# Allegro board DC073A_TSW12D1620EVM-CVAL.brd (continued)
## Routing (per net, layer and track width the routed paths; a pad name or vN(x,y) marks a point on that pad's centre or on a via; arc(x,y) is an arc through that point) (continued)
DQD5+: length 81.3
  L08_SIG2 w0.076: v1(131.44,94.72) 131.44,94.28 131.52,94.2 131.83,94.2 132.21,93.83 132.21,93.04 131.66,92.49 130.53,92.49 126.01,97.02 111.13,97.02 110.7,96.58 109.96,96.58 109.67,96.88 109.67,97.29 109.52,97.45 108.99,97.45 108.83,97.29 108.83,96.88 108.54,96.58 107.81,96.58 107.51,96.88 107.51,97.29 107.36,97.45 106.83,97.45 106.67,97.29 106.67,96.88 106.38,96.58 105.65,96.58 105.35,96.88 105.35,97.29 105.2,97.45 104.67,97.45 104.51,97.29 104.51,96.88 104.22,96.58 103.59,96.58 103.19,96.98 103.19,97.29 103.04,97.45 100.84,97.45 98.52,99.77 88.19,99.77 87.26,98.84 87.26,92.76 89.17,90.85 89.17,80.27 87.39,78.49 87.39,75.46 86.99,75.06 86.56,75.06 86.49,74.99 v1(86.49,74.55)
DQD5-: length 81.3
  L08_SIG2 w0.076: v1(131.44,93.45) 131.44,93.88 131.52,93.96 131.73,93.96 131.97,93.73 131.97,93.14 131.56,92.74 130.63,92.74 130.47,92.9 130.47,93.06 130.55,93.14 130.55,93.3 130.44,93.41 130.28,93.41 130.2,93.33 130.04,93.33 126.11,97.26 111.03,97.26 110.6,96.82 110.06,96.82 109.91,96.98 109.91,97.39 109.62,97.69 108.89,97.69 108.59,97.39 108.59,96.98 108.44,96.82 107.91,96.82 107.75,96.98 107.75,97.39 107.46,97.69 106.73,97.69 106.43,97.39 106.43,96.98 106.28,96.82 105.75,96.82 105.59,96.98 105.59,97.39 105.3,97.69 104.57,97.69 104.27,97.39 104.27,96.98 104.12,96.82 103.69,96.82 103.44,97.08 103.44,97.39 103.14,97.69 100.94,97.69 98.62,100.01 88.09,100.01 87.02,98.94 87.02,92.66 88.93,90.75 88.93,81.08 88.75,80.9 88.75,80.79 88.93,80.62 88.93,80.37 87.15,78.59 87.15,76.83 86.87,76.56 86.87,76.35 87.15,76.07 87.15,75.56 86.89,75.3 86.56,75.3 86.49,75.38 v1(86.49,75.82)
DQD6+: length 81.1
  L10_SIG3 w0.076: v1(87.76,73.28) 87.76,73.68 87.63,73.81 87.31,73.81 86.97,74.14 86.97,77.32 87.45,77.8 111.37,77.8 112.51,78.94 113.19,78.94 114.4,77.73 114.85,77.73 118.41,81.29 118.41,81.51 118.03,81.88 117.81,81.88 114.95,79.02 114.53,79.02 114.01,79.54 114.01,79.86 119.34,85.19 119.68,85.19 120.16,84.71 120.36,84.71 120.73,85.08 120.73,85.3 120.25,85.78 120.25,86.19 120.77,86.71 121.19,86.71 121.67,86.23 121.88,86.23 122.26,86.61 122.26,86.83 121.78,87.31 121.78,87.72 122.3,88.24 122.72,88.24 123.2,87.76 123.41,87.76 123.79,88.14 123.79,88.35 123.31,88.83 123.31,89.25 123.83,89.77 124.3,89.77 124.78,89.29 124.94,89.29 125.32,89.67 125.32,89.88 124.84,90.36 124.84,90.78 125.36,91.3 125.77,91.3 126.25,90.82 126.47,90.82 126.84,91.19 126.84,91.41 126.36,91.89 126.36,92.3 126.88,92.82 127.3,92.82 127.78,92.34 127.99,92.34 128.37,92.72 128.37,92.94 127.89,93.42 127.89,93.83 129.53,95.47 132.64,95.47 132.72,95.55 v1(132.72,95.99)
DQD6-: length 81.1
  L10_SIG3 w0.076: v1(87.76,74.55) 87.76,74.15 87.66,74.05 87.41,74.05 87.21,74.24 87.21,74.88 87.28,74.95 87.44,74.95 87.5,75.02 87.5,75.21 87.43,75.29 87.29,75.29 87.21,75.36 87.21,77.22 87.55,77.56 88.13,77.56 88.2,77.49 88.2,77.33 88.27,77.27 88.47,77.27 88.54,77.34 88.54,77.49 88.61,77.56 111.47,77.56 112.61,78.7 113.09,78.7 114.3,77.49 114.95,77.49 118.65,81.19 118.65,81.61 118.13,82.12 117.71,82.12 114.85,79.26 114.63,79.26 114.26,79.64 114.26,79.76 119.44,84.94 119.58,84.94 120.06,84.46 120.46,84.46 120.98,84.98 120.98,85.4 120.5,85.88 120.5,86.09 120.87,86.47 121.09,86.47 121.57,85.99 121.98,85.99 122.5,86.51 122.5,86.93 122.02,87.41 122.02,87.62 122.4,88 122.62,88 123.1,87.52 123.51,87.52 124.03,88.04 124.03,88.45 123.55,88.93 123.55,89.15 123.93,89.53 124.2,89.53 124.68,89.05 125.04,89.05 125.56,89.57 125.56,89.98 125.08,90.46 125.08,90.68 125.46,91.05 125.67,91.05 126.15,90.58 126.57,90.58 127.09,91.09 127.09,91.51 126.61,91.99 126.61,92.2 126.98,92.58 127.2,92.58 127.68,92.1 128.09,92.1 128.61,92.62 128.61,93.04 128.13,93.52 128.13,93.73 129.63,95.23 132.64,95.23 132.72,95.15 v1(132.72,94.72)
DQD7+: length 81.1
  L10_SIG3 w0.076: v1(136.53,94.72) 136.53,94.28 136.6,94.2 136.82,94.2 137.06,94.44 137.06,94.95 136.8,95.21 136.12,95.21 136.05,95.14 136.05,94.91 135.98,94.84 135.84,94.84 135.76,94.92 135.76,95.14 135.7,95.21 133.87,95.21 133.55,94.89 133.55,94.44 133.09,93.97 131.29,93.97 129.43,92.11 129.43,88.19 128.46,87.22 127.52,87.22 126.57,88.17 126.35,88.17 120.54,82.36 120.54,82.14 120.91,81.76 121.13,81.76 126.25,86.89 126.67,86.89 127.19,86.37 127.19,85.95 117.59,76.35 87.89,76.35 87.76,76.22 v1(87.76,75.82)
DQD7-: length 81.3
  L10_SIG3 w0.076: v1(87.76,77.09) 87.76,76.69 87.85,76.59 117.49,76.59 126.95,86.05 126.95,86.27 126.57,86.65 126.35,86.65 121.23,81.52 120.81,81.52 120.3,82.04 120.3,82.46 126.25,88.42 126.67,88.42 127.62,87.46 128.36,87.46 129.18,88.29 129.18,92.21 131.19,94.22 132.99,94.22 133.31,94.54 133.31,94.99 133.77,95.45 136.9,95.45 137.3,95.05 137.3,94.34 136.93,93.96 136.6,93.96 136.53,93.88 v1(136.53,93.45)
DQD8+: length 81.3
  L10_SIG3 w0.076: v1(89.03,74.55) 89.03,74.99 89.1,75.06 89.27,75.06 89.52,74.82 89.52,71.02 90.28,70.26 90.69,70.26 92.13,71.7 92.35,71.7 92.72,71.32 92.72,71.04 91.29,69.61 91.29,69.24 91.79,68.74 92.19,68.74 93.63,70.17 93.87,70.17 94.25,69.8 94.25,69.58 92.81,68.14 92.81,67.73 93.7,66.84 116.41,66.84 138.62,89.05 138.62,95.12 138.27,95.47 137.87,95.47 137.79,95.55 v1(137.79,95.99)
DQD8-: length 81.3
  L10_SIG3 w0.076: v1(89.03,75.82) 89.03,75.38 89.1,75.3 89.37,75.3 89.76,74.92 89.76,71.12 90.38,70.5 90.59,70.5 92.03,71.94 92.45,71.94 92.97,71.42 92.97,70.94 91.53,69.51 91.53,69.34 91.89,68.98 92.09,68.98 93.53,70.41 93.97,70.41 94.49,69.9 94.49,69.48 93.06,68.04 93.06,67.83 93.8,67.08 94.18,67.08 94.25,67.15 94.25,67.19 94.32,67.26 94.41,67.26 94.48,67.19 94.48,67.15 94.54,67.08 116.31,67.08 138.38,89.15 138.38,89.38 138.3,89.46 138.23,89.46 138.15,89.53 138.15,89.76 138.23,89.84 138.3,89.84 138.38,89.92 138.38,93.9 138.3,93.97 138.18,93.97 138.1,94.05 138.1,94.28 138.18,94.35 138.3,94.35 138.38,94.43 138.38,95.02 138.17,95.23 137.87,95.23 137.79,95.15 v1(137.79,94.72)
DQD9+: length 81.3
  L10_SIG3 w0.076: v1(90.3,73.28) 90.3,73.61 90.47,73.79 94.4,73.79 94.65,73.53 94.65,72.53 96.33,70.85 97.96,70.85 98.25,71.15 98.25,72.58 98.4,72.73 98.94,72.73 99.09,72.58 99.09,71.15 99.38,70.85 100.12,70.85 100.41,71.15 100.41,72.58 100.56,72.73 101.1,72.73 101.25,72.58 101.25,71.15 101.54,70.85 102.28,70.85 102.57,71.15 102.57,72.58 102.72,72.73 103.25,72.73 103.41,72.58 103.41,71.15 103.7,70.85 104.43,70.85 104.73,71.15 104.73,72.58 104.88,72.73 105.41,72.73 105.57,72.58 105.57,71.15 105.86,70.85 106.59,70.85 106.89,71.15 106.89,72.58 107.04,72.73 107.57,72.73 107.72,72.58 107.72,71.15 108.02,70.85 108.75,70.85 109.05,71.15 109.05,72.58 109.2,72.73 109.73,72.73 109.88,72.58 109.88,71.15 110.18,70.85 110.91,70.85 111.2,71.15 111.2,72.58 111.36,72.73 111.89,72.73 112.04,72.58 112.04,71.15 112.34,70.85 113.07,70.85 113.36,71.15 113.36,72.58 113.52,72.73 114.05,72.73 114.2,72.58 114.2,71.15 114.65,70.7 116.14,70.7 132.11,86.66 132.11,90.07 131.78,90.39 131.52,90.39 131.44,90.47 v1(131.44,90.91)
DQD9-: length 81.1
  L10_SIG3 w0.076: v1(131.44,89.64) 131.44,90.07 131.52,90.15 131.68,90.15 131.86,89.97 131.86,89.25 131.75,89.13 131.71,89.13 131.6,89.02 131.6,88.86 131.71,88.75 131.75,88.75 131.86,88.64 131.86,87.61 131.75,87.5 131.68,87.5 131.57,87.38 131.57,87.23 131.68,87.11 131.75,87.11 131.86,87 131.86,86.76 116.04,70.94 114.75,70.94 114.44,71.25 114.44,72.68 114.15,72.97 113.42,72.97 113.12,72.68 113.12,71.25 112.97,71.09 112.44,71.09 112.28,71.25 112.28,72.68 111.99,72.97 111.26,72.97 110.96,72.68 110.96,71.25 110.81,71.09 110.28,71.09 110.13,71.25 110.13,72.68 109.83,72.97 109.1,72.97 108.8,72.68 108.8,71.25 108.65,71.09 108.12,71.09 107.97,71.25 107.97,72.68 107.67,72.97 106.94,72.97 106.65,72.68 106.65,71.25 106.49,71.09 105.96,71.09 105.81,71.25 105.81,72.68 105.51,72.97 104.78,72.97 104.49,72.68 104.49,71.25 104.33,71.09 103.8,71.09 103.65,71.25 103.65,72.68 103.35,72.97 102.62,72.97 102.33,72.68 102.33,71.25 102.18,71.09 101.64,71.09 101.49,71.25 101.49,72.68 101.2,72.97 100.46,72.97 100.17,72.68 100.17,71.25 100.02,71.09 99.48,71.09 99.33,71.25 99.33,72.68 99.04,72.97 98.3,72.97 98.01,72.68 98.01,71.25 97.86,71.09 96.43,71.09 94.89,72.63 94.89,73.63 94.5,74.03 90.37,74.03 90.36,74.02 90.3,74.09 v1(90.3,74.55)
DQD10+: length 81.2
  L10_SIG3 w0.076: v1(91.57,74.55) 91.07,75.04 91.07,75.15 91.15,75.23 91.32,75.23 91.58,74.97 95.69,74.97 97.07,73.6 97.72,73.6 98.02,73.89 98.02,75.25 98.17,75.4 98.7,75.4 98.86,75.25 98.86,73.89 99.15,73.6 99.88,73.6 100.18,73.89 100.18,75.25 100.33,75.4 100.86,75.4 101.05,75.21 101.05,73.85 101.31,73.6 102.04,73.6 102.34,73.89 102.34,75.25 102.49,75.4 103.02,75.4 103.17,75.25 103.17,73.89 103.47,73.6 104.2,73.6 104.5,73.89 104.5,75.25 104.65,75.4 105.18,75.4 105.33,75.25 105.33,73.89 105.63,73.6 106.36,73.6 106.65,73.89 106.65,75.25 106.81,75.4 107.34,75.4 107.49,75.25 107.49,73.89 107.79,73.6 108.52,73.6 108.81,73.89 108.81,75.25 108.97,75.4 109.5,75.4 109.65,75.25 109.65,73.89 109.94,73.6 110.68,73.6 110.97,73.89 110.97,75.25 111.12,75.4 111.66,75.4 111.81,75.25 111.81,73.89 112.1,73.6 112.84,73.6 113.13,73.89 113.13,75.25 113.28,75.4 113.82,75.4 113.97,75.25 113.97,73.89 114.26,73.6 116.73,73.6 130.62,87.49 130.62,90.33 130.69,90.4 130.79,90.4 130.86,90.46 130.86,90.56 130.79,90.62 130.69,90.62 130.62,90.69 130.62,90.93 131.7,92.01 131.79,92.01 132,91.8 132.11,91.8 132.21,91.9 132.21,92.04 132.01,92.23 132.01,92.33 132.36,92.67 133.1,92.67 133.29,92.48 133.29,91.9 133.05,91.66 132.79,91.66 132.72,91.74 v1(132.72,92.18)
DQD10-: length 81.1
  L10_SIG3 w0.076: v1(132.72,90.91) 132.72,91.34 132.79,91.42 133.15,91.42 133.53,91.8 133.53,92.58 133.2,92.91 132.26,92.91 130.38,91.03 130.38,87.59 116.63,73.84 114.36,73.84 114.21,73.99 114.21,75.35 113.92,75.64 113.18,75.64 112.89,75.35 112.89,73.99 112.74,73.84 112.2,73.84 112.05,73.99 112.05,75.35 111.76,75.64 111.02,75.64 110.73,75.35 110.73,73.99 110.58,73.84 110.04,73.84 109.89,73.99 109.89,75.35 109.6,75.64 108.87,75.64 108.57,75.35 108.57,73.99 108.42,73.84 107.89,73.84 107.73,73.99 107.73,75.35 107.44,75.64 106.71,75.64 106.41,75.35 106.41,73.99 106.26,73.84 105.73,73.84 105.57,73.99 105.57,75.35 105.28,75.64 104.55,75.64 104.25,75.35 104.25,73.99 104.1,73.84 103.57,73.84 103.42,73.99 103.42,75.35 103.12,75.64 102.39,75.64 102.09,75.35 102.09,73.99 101.94,73.84 101.41,73.84 101.3,73.95 101.3,75.31 100.96,75.64 100.23,75.64 99.94,75.35 99.94,73.99 99.78,73.84 99.25,73.84 99.1,73.99 99.1,75.35 98.8,75.64 98.07,75.64 97.78,75.35 97.78,73.99 97.62,73.84 97.17,73.84 95.79,75.21 91.68,75.21 91.42,75.47 91.05,75.47 90.9,75.32 90.79,75.32 v1(90.3,75.82)
DQD11+: length 81.3
  L10_SIG3 w0.076: v1(136.53,90.91) 136.53,90.47 136.6,90.39 136.96,90.39 137.21,90.14 137.21,89.31 136.73,88.82 134.89,88.82 133.38,87.31 133.38,85.87 132.11,84.6 132.11,84.28 131.72,83.9 131.41,83.9 115.96,68.45 115.14,68.45 114.48,69.11 114.48,69.74 114.33,69.89 113.8,69.89 113.65,69.74 113.65,68.48 113.35,68.19 112.62,68.19 112.33,68.48 112.33,69.74 112.17,69.89 111.64,69.89 111.49,69.74 111.49,68.48 111.19,68.19 110.46,68.19 110.17,68.48 110.17,69.74 110.01,69.89 109.48,69.89 109.33,69.74 109.33,68.48 109.03,68.19 108.3,68.19 108.01,68.48 108.01,69.74 107.85,69.89 107.32,69.89 107.17,69.74 107.17,68.48 106.88,68.19 106.14,68.19 105.85,68.48 105.85,69.74 105.7,69.89 105.16,69.89 105.01,69.74 105.01,68.48 104.72,68.19 103.98,68.19 103.69,68.48 103.69,69.74 103.54,69.89 103,69.89 102.85,69.74 102.85,68.48 102.56,68.19 101.82,68.19 101.53,68.48 101.53,69.74 101.38,69.89 100.84,69.89 100.69,69.74 100.69,68.48 100.4,68.19 99.66,68.19 99.37,68.48 99.37,69.74 99.22,69.89 98.69,69.89 98.45,69.65 98.45,68.61 98.03,68.19 97.32,68.19 93.35,72.16 93.35,73.16 93.24,73.28 v1(92.84,73.28)
DQD11-: length 81.3
  L10_SIG3 w0.076: v1(136.53,89.64) 136.53,90.07 136.6,90.15 136.86,90.15 136.97,90.04 136.97,89.41 136.63,89.07 136.17,89.07 136.1,89.14 136.1,89.33 136.02,89.41 135.79,89.41 135.72,89.33 135.72,89.14 135.64,89.07 134.79,89.07 133.13,87.41 133.13,85.97 131.86,84.7 131.86,84.38 131.62,84.14 131.31,84.14 116.35,69.18 116.25,69.18 116.22,69.21 116.13,69.21 116.06,69.15 116.06,69.05 116.09,69.02 116.09,68.92 115.86,68.69 115.24,68.69 114.73,69.21 114.73,69.84 114.43,70.13 113.7,70.13 113.4,69.84 113.4,68.58 113.25,68.43 112.72,68.43 112.57,68.58 112.57,69.84 112.27,70.13 111.54,70.13 111.25,69.84 111.25,68.58 111.09,68.43 110.56,68.43 110.41,68.58 110.41,69.84 110.11,70.13 109.38,70.13 109.09,69.84 109.09,68.58 108.93,68.43 108.4,68.43 108.25,68.58 108.25,69.84 107.95,70.13 107.22,70.13 106.93,69.84 106.93,68.58 106.78,68.43 106.24,68.43 106.09,68.58 106.09,69.84 105.8,70.13 105.06,70.13 104.77,69.84 104.77,68.58 104.62,68.43 104.08,68.43 103.93,68.58 103.93,69.84 103.64,70.13 102.9,70.13 102.61,69.84 102.61,68.58 102.46,68.43 101.92,68.43 101.77,68.58 101.77,69.84 101.48,70.13 100.74,70.13 100.45,69.84 100.45,68.58 100.3,68.43 99.76,68.43 99.61,68.58 99.61,69.84 99.32,70.13 98.59,70.13 98.21,69.75 98.21,69.28 98.14,69.21 98.09,69.21 98.02,69.15 98.02,69.05 98.09,68.99 98.14,68.99 98.21,68.92 98.21,68.71 97.93,68.43 97.42,68.43 94.25,71.6 94.25,71.76 94.29,71.8 94.29,71.96 94.17,72.07 94.02,72.07 93.98,72.03 93.82,72.03 93.59,72.26 93.59,73.16 93.71,73.28 v1(94.11,73.28)
ECEN: length 58.7
  L10_SIG3 w0.127: JP8.2 69.29,145.08 72.85,145.08 78.16,139.78 78.16,132.36 76.17,130.38 76.17,113.56 73.55,110.93 73.55,106.74 73.18,106.38 73.18,96.77 73.79,96.16 v1(73.79,96.14)
EE_ADDR0_RX: length 52.3
  L08_SIG2 w0.127: v1(108.75,39.47) 108.75,39.48 108.51,39.73 108.51,42.72 109.32,43.54 109.32,46.04 108.66,46.7 108.66,47.98 109.42,48.74 114.38,48.74 115.8,50.16 131.9,50.16 136.12,54.38 136.12,54.97 136.98,55.83 139.29,55.83 139.67,56.21 139.67,63.58 v1(140.34,64.24)
EE_ADDR1_RX: length 49.9
  L08_SIG2 w0.127: v1(108.75,38.2) 106.83,40.12 106.83,47.17 109.52,49.86 114.99,49.86 116.05,50.93 129.41,50.93 132.77,54.29 132.77,54.81 134.15,56.2 134.16,56.2 135.67,57.71 135.67,57.72 136.69,58.74 136.7,58.74 136.94,58.98 136.94,58.99 137.26,59.31 137.26,60.5 139.06,62.31 v1(139.06,62.97)
EECLK: length 9.1
  BOTTOM w0.152: R146.2 27.66,32.64 25.07,35.22 U13.2 25.07,37.67 25.65,38.25 25.65,39.92 U12.62
EECS: length 10.3
  BOTTOM w0.152: R147.2 24.42,35.14 U13.1 24.42,37.91 25.2,38.69 U12.63
EEDATA: length 7.9
  BOTTOM w0.152: U12.61 26.2,38.21 25.76,37.77 25.76,36.14 U13.3 25.73,35.26 27.2,33.78 R157.1
FB+: length 3.1
  TOP w0.381: U1.4 52.17,109.89 52.75,110.46 C3.1
FB-: length 3.1
  TOP w0.381: C13.1 48.91,106.62 R11.2 U1.7
FBQ+: length 3.1
  TOP w0.381: U2.4 50.94,64.93 R17.2 48.93,64.07 C18.1
FBQ-: length 3.1
  TOP w0.381: U2.7 53.63,62.24 R24.2 52.77,60.23 52.77,59.94
FMC_ADC_SCSB: length 84.3
  L08_SIG2 w0.127: v1(63.88,26.04) 64.24,26.39 74.9,26.39 77.8,29.29 78.56,29.29 88.93,39.65 92.61,39.65 103.86,50.9 113.64,50.9 122.02,59.28 130.12,59.28 130.67,58.74 133.49,58.74 133.91,59.16 v1(133.99,59.16)
FMC_ADC_SDI: length 93.6
  L08_SIG2 w0.127: v1(63.88,27.69) 63.56,27.69 63.25,27.37 63.25,25.68 63.56,25.36 75.73,25.36 89.15,38.79 96.42,38.79 100.15,42.52 100.15,45.03 105.44,50.32 113.87,50.32 120.88,57.33 134.1,57.33 135.92,59.14 135.92,61.19 135.41,61.7 v1(135.25,61.7)
FMC_DATA: length 117.7
  TOP w0.152: v1(38.99,49.02) 40.49,49.02 52.6,36.91 55.45,36.91 57.81,34.54 59.33,34.54 63.88,30 v1(63.88,29.34)
  L08_SIG2 w0.127: v1(135.25,60.43) 134.67,59.84 121.67,59.84 114.3,52.48 104.55,52.48 92.46,40.39 88.7,40.39 78.64,30.33 74.7,30.33 73.99,29.62 64.16,29.62 v1(63.88,29.34)
FMC_LMX_CAL: length 132.1
  BOTTOM w0.254: v1(38.99,43.94) 39.9,43.94 46.69,50.72 128.04,50.72 130.05,52.73 130.05,86.87 130.85,87.67 132.02,87.67 v1(132.72,88.37)
FMC_LMX_SCSB: length 104.1
  L10_SIG3 w0.127: v1(38.99,46.48) 42.01,46.48 48.56,53.04 113.11,53.04 124.89,64.82 134.54,64.82 135.23,65.51 v1(135.25,65.51)
FMC_LMX_SDI: length 124.6
  L10_SIG3 w0.127: v1(135.25,83.29) 136.07,82.47 136.07,65.64 134.05,63.63 124.94,63.63 113.61,52.3 48.74,52.3 v1(38.99,42.55)
FMC_SCL: length 71.2
  TOP w0.152: v1(101.46,36.93) 92.56,36.93 J30.2
  L05_SIG1 w0.127: v1(101.46,36.93) 101.78,36.93 109.3,44.45 109.3,45.19 108.36,46.13 108.36,48.44 108.81,48.89 108.81,49.2 117.47,57.86 130.71,57.86 131.58,58.74 131.62,58.74 131.86,58.98 131.86,59.02 132.85,60.01 132.89,60.01 133.13,60.25 133.13,60.29 134.12,61.28 134.16,61.28 135.89,63.01 135.89,64.26 138.38,66.75 138.38,68.1 138.94,68.66 139.67,68.66 v1(140.34,69.32)
FMC_SCLK: length 116.3
  TOP w0.152: v1(63.88,30.99) 60.05,34.82 60.05,35.99 57.73,38.3 52.37,38.3 40.26,50.42 v1(38.99,50.42)
  L08_SIG2 w0.127: v1(63.88,30.99) 78.38,30.99 100.46,53.06 114.07,53.06 121.44,60.43 132,60.43 132.42,60.85 133.57,60.85 v1(133.99,60.43)
FMC_SDA: length 74.4
  TOP w0.152: v1(101.46,35.66) 92.2,35.66 90.7,34.16 90.7,33.35 89.87,32.51 87.88,32.51 J30.1
  L05_SIG1 w0.127: v1(140.34,68.05) 139.65,67.36 139.65,65.41 131.54,57.3 117.65,57.3 108.66,48.31 108.66,46.7 109.68,45.68 109.68,43.88 v1(101.46,35.66)
FSR: length 87.5
  L10_SIG3 w0.127: JP6.2 76.96,146.33 75.87,147.42 67.64,147.42 66.73,146.51 66.73,131.8 68,130.53 68,114.27 71.98,110.29 71.98,106.72 72,106.71 72,106.34 71.98,106.33 71.98,106.13 72.07,106.04 72.07,105.69 71.77,105.39 71.77,100.47 71.98,100.25 71.98,96.06 73.33,94.72 73.33,73.74 v1(73.79,73.28)
FTDI_ADC_DATA: length 51.3
  L10_SIG3 w0.127: v1(23.79,51.22) 25.22,52.65 28.63,52.65 30,51.28 30,50.5 31.62,48.87 31.62,47.32 33.71,45.24 33.71,44.09 41.17,36.63 43.56,36.63 49.82,30.37 56.25,30.37 57.28,29.34 v1(61.85,29.34)
  BOTTOM w0.152: U12.17 v1(23.79,51.22)
FTDI_ADC_SCLK: length 55.2
  L10_SIG3 w0.127: v1(24.35,49.34) 24.35,50.03 25.88,51.56 26.72,51.56 27.99,50.29 27.99,47.12 30.4,44.7 30.99,44.7 31.37,44.32 32.72,44.32 34.49,42.55 34.49,42.19 40.56,36.12 42.98,36.12 50.47,28.63 62.26,28.63 62.71,29.08 62.71,30.12 v1(61.85,30.99)
  BOTTOM w0.152: U12.16 v1(24.35,49.34)
FTDI_ADC_SCSB: length 51
  L10_SIG3 w0.127: v1(26.11,49.02) 26.11,47.07 29.9,43.28 31.37,43.28 33.66,41 33.66,39.88 34.29,39.24 34.29,38.23 35.81,36.7 35.81,35.08 38.63,32.26 45.29,32.26 50.98,26.57 61.39,26.57 61.85,26.11 v1(61.85,26.04)
  BOTTOM w0.152: U12.19 25.7,49.44 v1(26.11,49.02)
FTDI_ADC_SDI: length 52.6
  L10_SIG3 w0.127: v1(61.85,27.69) 61.49,28.04 50.32,28.04 42.81,35.55 40.32,35.55 38.44,37.43 35.75,37.43 34.8,38.38 34.8,41.22 34.06,41.96 33.86,41.96 33.6,42.21 33.6,42.6 32.54,43.66 30.56,43.66 27.64,46.58 27.64,49.99 26.8,50.83 25.93,50.83 25.2,50.09 v1(25.2,49.58)
  BOTTOM w0.152: U12.18 v1(25.2,49.58)
IN+: length 6.2
  TOP w0.381: U1.6 50.38,108.09 R6.1 50.2,108.27 R7.2 48.76,108.63 R11.1 48.19,107.34 C13.2
IN-: length 6.2
  TOP w0.381: U1.5 51.28,108.99 R6.2 51.1,109.17 R3.2 50.74,110.61 R2.1 52.03,111.18 C3.2
INI_+: length 9.3
  TOP w0.381: R1.1 66.04,96.81 66.04,102.51 J1.1
INI_-: length 9.2
  TOP w0.381: J3.1 56.88,93.34 62.57,93.34 R12.1
INQ_+: length 9.2
  TOP w0.381: J4.1 56.9,77.34 62.6,77.34 R16.1
INQ_-: length 9.2
  TOP w0.381: R27.1 66.04,73.9 66.04,68.17 J6.1
IPD: length 9.2
  TOP w0.381: JP1.2 45.56,106.81 46.79,106.81 50.11,103.48 50.11,103.45 50.5,103.07 51.56,103.07 52.02,103.53 U1.9
  vias: v1(52.47,103.91)
LMX_CAL: length 99.9
  L08_SIG2 w0.127: v4(24.28,135.86) 24.28,134.26 21.54,131.52 21.54,114.58 31.65,104.47 31.65,62.1 35.46,58.29 35.46,46.35 37.87,43.94 v1(37.97,43.94)
LMX_CLKM: length 58.5
  L10_SIG3 w0.076: v5(67.76,83.1) 66.78,82.12 66.61,82.12 61.67,87.06 56.22,87.06 34.76,108.52 34.76,110.95 28.09,117.61 28.09,118.11 28.32,118.34 29.18,118.34 v5(29.59,118.75)
LMX_CLKP: length 58.5
  L10_SIG3 w0.076: v5(26.42,118.75) 26.85,118.31 27.63,118.31 27.85,118.1 27.85,117.51 34.52,110.85 34.52,108.42 56.12,86.82 61.57,86.82 66.4,81.99 66.4,81.74 v5(65.52,80.86)
LMX_CSB: length 98.5
  TOP w0.152: v1(37.97,46.48) 39.75,44.7 39.75,37.8 42.04,35.51 TP8.1
  L08_SIG2 w0.127: v1(37.97,46.48) 37.9,46.48 36.58,47.8 36.58,59.89 33.64,62.83 33.64,86.53 33.77,86.65 33.77,88.48 33.01,89.24 33.01,100.95 33.79,101.74 33.79,102.93 33.6,103.12 33.6,114.51 33.1,115.02 33.1,116.56 33.76,117.22 33.76,117.67 33.74,117.68 33.74,117.82 30.97,120.6 27.1,120.6 v1(26.79,120.28)
  BOTTOM w0.152: U7.39 v1(26.79,120.28)
LMX_OSCN: length 2.6
  BOTTOM w0.178: U7.13 28.29,137.19 28.21,137.27 28.21,138.19 C135.1
LMX_OSCP: length 2.6
  BOTTOM w0.178: C128.1 27.87,138.12 27.87,137.21 27.79,137.13 U7.12
LMX_SCK: length 89.8
  TOP w0.152: TP6.1 41.94,42.9 41.94,45.11 38.53,48.51 38.53,49.81 37.97,50.37 v1(37.97,50.42)
  L08_SIG2 w0.127: v1(37.97,50.42) 37.97,60.81 35.26,63.53 35.26,103 35.74,103.48 35.74,112.9 35.26,113.39 35.26,121.23 35.69,121.67 35.69,124.89 33.71,126.87 33.71,128.07 v4(33.48,128.3)
LMX_SDI: length 94.1
  TOP w0.152: TP7.1 40.36,40.03 40.36,46 37.97,48.39 v1(37.97,49.02)
  L08_SIG2 w0.127: v1(37.97,49.02) 37.95,49.02 37.08,49.89 37.08,56.17 37.67,56.75 37.67,57.3 37.36,57.6 37.36,60.63 34.21,63.78 34.21,116.46 34.62,116.87 34.62,125.22 32.77,127.08 v4(32.77,127.79)
LMX_SDO: length 79.8
  L08_SIG2 w0.127: v1(33.02,117.86) 32.56,117.4 32.56,114.88 32.92,114.52 32.92,111.63 31.85,110.57 31.85,104.93 32.44,104.35 32.44,86.08 32.65,85.86 32.65,83.76 32.44,83.54 32.44,62.94 35.13,60.25 35.13,59.39 36.02,58.5 36.02,47.02 37.26,45.77 38.1,45.77 38.53,45.34 38.53,43.08 38,42.55 v1(37.97,42.55)
LMX_SYNC: length 11.1
  BOTTOM w0.152: U7.9 26.29,138.55 R102.1 26.82,139.09 29.67,139.09 32.44,141.86 v1(33.66,141.86)
LSPSM: length 77.1
  L10_SIG3 w0.127: JP3.2 87.76,143.76 87.76,129.62 83.59,125.45 83.59,113.61 81.39,111.42 81.39,108.47 81.74,108.13 81.74,100.97 75.54,94.77 75.54,76.33 75.06,75.84 v1(75.06,75.82)
MISO: length 85.8
  L10_SIG3 w0.127: v1(8.76,104.95) 9.58,104.14 9.58,102.36 9.17,101.96 9.17,73 9.98,72.19 9.98,57.12 10.39,56.72 10.39,44.22 18.49,36.12 28.88,36.12 v1(29.59,36.83)
  BOTTOM w0.152: v1(8.76,104.95) 8.95,105.14 U20.21
MOSI: length 86.9
  L10_SIG3 w0.127: v1(8.94,103.66) 8.59,103.3 8.59,72.92 9.27,72.24 9.27,56.85 9.88,56.24 9.88,43.92 18.19,35.61 29.51,35.61 v1(30.73,36.83)
  BOTTOM w0.152: v1(8.94,103.66) 8.94,104.24 9.34,104.64 U20.20
MUX_OUT: length 15.8
  BOTTOM w0.279: R107.1 R105.1 32.39,118.87 30.61,117.09 TP9.1
  BOTTOM w0.305: R105.1 33.02,121.01 33.19,121.17 U7.32
NDM: length 52.9
  L10_SIG3 w0.127: v1(76.33,97.41) 76.33,98.42 80.26,102.36 80.26,112.59 82.22,114.55 82.22,126.29 81.43,127.08 81.43,130.12 82.88,131.57 82.88,144.86 81.43,146.3 JP5.2
Net_2:
  vias: v1(133.99,99.8)
Net_63:
  vias: v1(135.25,64.24)
Net_159:
  vias: v1(142.88,94.72)
Net_160:
  vias: v1(142.88,93.45)
Net_161:
  vias: v1(140.34,99.8)
Net_162:
  vias: v1(140.34,98.53)
Net_163:
  vias: v1(141.6,90.91)
Net_164:
  vias: v1(141.6,92.18)
Net_165:
  vias: v1(142.88,88.37)
Net_166:
  vias: v1(142.88,83.29)
Net_167:
  vias: v1(142.88,84.56)
Net_168:
  vias: v1(142.88,104.88)
Net_169:
  vias: v1(142.88,103.61)
Net_170:
  vias: v1(142.88,99.8)
Net_171:
  vias: v1(142.88,98.53)
Net_172:
  vias: v1(141.6,85.83)
Net_173:
  vias: v1(141.6,87.1)
Net_174:
  vias: v1(142.88,89.64)
Net_175:
  vias: v1(141.6,97.26)
Net_176:
  vias: v1(141.6,101.07)
Net_177:
  vias: v1(141.6,102.34)
Net_178:
  vias: v1(141.6,95.99)
Net_179:
  vias: v1(139.06,102.34)
Net_180:
  vias: v1(139.06,101.07)
Net_500:
  vias: v1(131.44,101.07)
Net_501:
  vias: v1(131.44,102.34)
Net_502:
  vias: v1(131.44,59.16)
Net_509:
  vias: v1(131.44,104.88)
Net_514:
  vias: v1(131.44,106.15)
Net_516:
  vias: v1(132.72,60.43)
Net_519:
  vias: v1(132.72,65.51)
Net_524:
  vias: v1(132.72,104.88)
Net_526:
  vias: v1(132.72,84.56)
Net_528:
  vias: v1(132.72,87.1)
Net_529:
  vias: v1(133.99,101.07)
Net_530:
  vias: v1(133.99,102.34)
Net_534:
  vias: v1(133.99,106.15)
Net_535:
  vias: v1(135.25,103.61)
Net_536:
  vias: v1(135.25,104.88)
Net_539:
  vias: v1(136.53,59.16)
Net_540:
  vias: v1(136.53,60.43)
Net_541:
  vias: v1(136.53,62.97)
Net_542:
  vias: v1(136.53,64.24)
Net_543:
  vias: v1(136.53,82.02)
Net_544:
  vias: v1(136.53,83.29)
Net_545:
  vias: v1(136.53,85.83)
Net_548:
  vias: v1(137.79,60.43)
Net_549:
  vias: v1(137.79,61.7)
Net_550:
  vias: v1(137.79,64.24)
Net_551:
  vias: v1(137.79,65.51)
Net_552:
  vias: v1(137.79,83.29)
Net_553:
  vias: v1(137.79,84.56)
Net_554:
  vias: v1(137.79,87.1)
Net_557:
  vias: v1(137.79,90.91)
Net_558:
  vias: v1(137.79,92.18)
Net_559:
  vias: v1(139.06,64.24)
Net_560:
  vias: v1(139.06,65.51)
Net_561:
  vias: v1(139.06,70.59)
Net_564:
  vias: v1(139.06,85.83)
Net_565:
  vias: v1(140.34,103.61)
Net_567:
  vias: v1(140.34,104.88)
Net_569:
  vias: v1(140.34,84.56)
Net_570:
  vias: v1(141.6,56.62)
Net_571:
  vias: v1(141.6,60.43)
Net_572:
  vias: v1(141.6,61.7)
Net_573:
  vias: v1(141.6,65.51)
Net_574:
  vias: v1(141.6,66.78)
Net_575:
  vias: v1(141.6,70.59)
Net_576:
  vias: v1(141.6,71.86)
Net_579:
  vias: v1(141.6,80.75)
Net_581:
  vias: v1(141.6,106.15)
Net_582:
  vias: v1(142.88,57.89)
Net_583:
  vias: v1(142.88,59.16)
Net_584:
  vias: v1(142.88,62.97)
Net_585:
  vias: v1(142.88,64.24)
Net_586:
  vias: v1(142.88,68.05)
Net_587:
  vias: v1(142.88,69.32)
Net_588:
  vias: v1(142.88,73.13)
Net_589:
  vias: v1(142.88,74.4)
Net_590:
  vias: v1(142.88,78.21)
Net_591:
  vias: v1(142.88,79.48)
ORI+:
  vias: v1(133.99,64.24)
ORI-:
  vias: v1(133.99,62.97)
ORQ+:
  vias: v1(137.79,69.32)
ORQ-:
  vias: v1(137.79,68.05)
OSCI: length 9.3
  BOTTOM w0.178: Y2.2 19.32,40.24 19.5,40.42 19.5,41.85 19.76,42.11 21.18,42.11 21.47,42.39 22.77,42.39 U12.2
  BOTTOM w0.381: C174.1 15.29,40.24 Y2.2
OSCO: length 9.3
  BOTTOM w0.178: U12.3 22.78,42.8 21.39,42.8 21.04,42.45 19.78,42.45 19.56,42.67 19.56,43.98 19.21,44.34 Y2.1
  BOTTOM w0.381: C175.1 15.28,44.34 Y2.1
OUT+: length 2.1
  TOP w0.381: R4.1 U1.13
OUT-: length 2.1
  TOP w0.381: R9.1 U1.12
OUTQ+: length 2.1
  TOP w0.381: U2.13 R19.1
OUTQ-: length 2.1
  TOP w0.381: R23.1 56.13,66.53 U2.12
OVRI+: length 88
  L10_SIG3 w0.076: v1(27.69,64.24) 26.78,62.95 26.8,62.85 26.83,62.81 27.37,62.28 46.95,62.28 48.08,63.41 52.76,63.41 58.28,68.94 60.61,68.94 63.02,66.52 64.17,66.52 66.23,68.58 73.03,68.58 73.34,68.9 73.34,69.15 73.41,69.22 73.66,69.22 76.91,72.47 76.91,78.84 76.47,79.29 76.47,84.7 77.75,85.99 88.46,85.99 88.46,85.99 88.67,85.99 89.1,85.56 89.37,85.56 v1(89.63,85.81)
  BOTTOM w0.102: v1(89.63,85.81) 89.87,85.57 90.23,85.57 90.29,85.63 90.29,85.82 90.35,85.88 90.43,85.88 90.49,85.82 90.49,85.63 90.78,85.34 91.24,85.34 91.41,85.51 91.41,85.6 91.03,85.98 R56.2
OVRI-: length 91.5
  TOP w0.305: U3.2 24.38,61.21 C32.2 v1(25.65,61.34)
  L10_SIG3 w0.076: v1(25.65,61.34) 26.56,62.63 26.66,62.64 27.27,62.04 47.05,62.04 48.18,63.17 52.86,63.17 58.38,68.69 60.51,68.69 62.92,66.28 64.27,66.28 66.33,68.34 73.13,68.34 77.15,72.37 77.15,78.94 76.71,79.39 76.71,84.6 77.85,85.75 88.56,85.75 88.56,85.75 88.57,85.75 89,85.32 89.37,85.32 v1(89.63,85.07)
  BOTTOM w0.102: v1(89.63,85.07) 89.86,85.31 90.44,85.31 90.67,85.08 91.35,85.08 91.68,85.4 91.68,85.5 92.15,85.98 R55.2
OVRQ+: length 97.1
  L10_SIG3 w0.076: v1(17.12,66.07) 17.12,64.87 17.45,64.54 19.19,64.54 23.46,60.27 23.82,60.27 23.92,60.38 24.08,60.38 24.18,60.27 46.82,60.27 46.98,60.11 47.35,60.11 47.61,60.36 53.55,60.36 53.79,60.6 66.92,60.6 67.26,60.95 67.26,61.04 67.26,61.04 67.26,61.14 67.33,61.21 67.42,61.21 67.42,61.2 67.52,61.2 77.61,71.29 77.61,71.5 77.68,71.58 77.89,71.58 78.12,71.8 78.12,79.21 77.3,80.02 77.3,83.27 78.02,83.99 88.46,83.99 88.51,84.04 89.41,84.04 v1(89.66,84.29)
  BOTTOM w0.102: v1(89.66,84.29) 89.9,84.05 90.18,84.05 90.24,84.11 90.24,84.32 90.3,84.38 90.38,84.38 90.44,84.32 90.44,84.11 90.5,84.05 91.3,84.05 91.4,84.15 91.4,84.29 90.98,84.71 R57.2
OVRQ-: length 100.5
  TOP w0.305: U3.6 15.24,62.48 C33.2 R36.1
  L10_SIG3 w0.076: v1(89.66,83.54) 89.41,83.79 88.61,83.79 88.56,83.75 78.12,83.75 77.55,83.17 77.55,80.12 78.36,79.31 78.36,71.7 67.02,60.36 53.89,60.36 53.65,60.12 47.71,60.12 47.45,59.87 46.88,59.87 46.72,60.03 23.36,60.03 19.09,64.3 17.56,64.3 17.37,64.11 v1(18.21,62.48)
  BOTTOM w0.102: R54.2 92.16,84.71 91.67,84.21 91.67,84.04 91.41,83.78 89.9,83.78 v1(89.66,83.54)
PDI: length 66
  L08_SIG2 w0.127: J7.2 76.71,131.95 76.71,120.78 76.17,120.24 76.17,106.35 70.82,100.99 70.82,80.67 73.79,77.7 v1(73.79,77.09)
  BOTTOM w0.152: R32.1 J7.2
PDQ: length 70.6
  L08_SIG2 w0.127: v1(73.79,75.82) 73.71,75.82 73.1,76.43 72.39,76.43 70.1,78.71 70.1,79.24 69.89,79.46 69.89,79.8 70.1,80.02 70.1,80.51 69.89,80.73 69.89,81.07 70.1,81.29 70.1,89.4 69.89,89.62 69.89,89.96 70.1,90.18 70.1,90.67 69.89,90.89 69.89,91.23 70.1,91.45 70.1,91.94 69.89,92.16 69.89,92.5 70.1,92.72 70.1,93.21 69.89,93.43 69.89,93.77 70.1,93.99 70.1,102.51 74.97,107.38 74.97,107.73 75.23,107.99 75.58,107.99 75.62,108.03 75.62,124.84 72.09,128.37 72.09,132.33 68.28,136.14 J8.2
  BOTTOM w0.152: R33.1 J8.2
PG_RX1: length 74.7
  L10_SIG3 w0.127: v1(136.53,106.15) 136.94,106.57 138.09,106.57 138.43,106.22 138.43,105.82 138.84,105.41 139.12,105.41 142.27,102.27 142.27,55.91 139.7,53.34 136.37,53.34 135.99,52.96 129.41,52.96 128.68,52.22 124.56,52.22 J29.2
PRSNT_M2C_L: length 3.1
  TOP w0.279: v1(133.99,104.88) 133.35,105.51 133.35,107.21 R113.1
QN+: length 5.8
  TOP w0.381: C23.2 52.05,59.51 R24.1 51.12,60.08 R25.2 50.4,60.88 R22.1 52.66,63.14 U2.6
QN-: length 6
  TOP w0.381: 48.21,63.64 48.21,63.35 R17.1 48.78,62.42 R18.2 49.69,61.61 R22.2 50.45,62.54 51.84,63.93 U2.5
QPD: length 9.4
  TOP w0.381: U2.9 55.88,63.42 56.39,62.92 56.39,61.98 53.11,58.7 53.11,56.83 JP2.2
  vias: v1(55.48,63.78)
RCLK+: length 24.4
  L05_SIG1 w0.076: v1(71.88,57.4) 78.04,57.4 78.11,57.48 78.11,70.65 75.73,73.03 75.73,73.71 75.66,73.77 75.55,73.77 v1(75.06,73.28)
RCLK-: length 24.6
  L05_SIG1 w0.076: v1(84.58,57.4) 78.43,57.4 78.35,57.48 78.35,70.75 75.97,73.13 75.97,73.81 75.83,73.95 75.83,74.05 v1(76.33,74.55)
RCOUT1+: length 43.1
  L08_SIG2 w0.076: v1(97.28,57.4) 103.44,57.4 103.51,57.48 103.51,58.72 99.11,63.12 94.06,63.12 84.45,72.72 84.45,73.27 83.93,73.8 83.76,73.8 83.2,74.36 83.2,74.53 82.68,75.05 77,75.05 76.9,75 v1(76.33,73.28)
RCOUT1-: length 43.4
  L08_SIG2 w0.076: v1(77.6,77.09) 77.02,75.37 77.07,75.29 82.78,75.29 83.44,74.63 83.44,74.46 83.86,74.04 84.03,74.04 84.7,73.37 84.7,72.82 94.16,63.36 99.21,63.36 103.75,58.82 103.75,57.48 103.83,57.4 v1(109.98,57.4)
RCOUT2+: length 49.1
  L05_SIG1 w0.076: v1(94.74,44.7) 100.81,44.7 100.97,44.86 100.97,50.87 89.23,62.61 89.23,65.08 84.56,69.74 81.26,69.74 78.11,72.89 78.11,75.74 78.04,75.82 v1(77.6,75.82)
RCOUT2-: length 49.1
  L05_SIG1 w0.076: v1(107.44,44.7) 101.37,44.7 101.21,44.86 101.21,50.97 89.47,62.71 89.47,65.18 84.66,69.98 81.36,69.98 78.35,72.99 78.35,75.74 78.43,75.82 v1(78.87,75.82)
RECAL_EN: length 3.7
  BOTTOM w0.203: U7.45 23.78,120.18 R110.2 R111.1
SCLK: length 74
  L08_SIG2 w0.127: v1(18.87,105.21) 18.87,104.6 30.2,93.27 30.2,87.05 31.11,86.13 31.11,61.95 31.39,61.67 31.39,60.5 34.33,57.57 34.33,48.54 34.39,48.47 34.39,48.21 34.33,48.15 34.33,47.54 34.39,47.47 34.39,47.21 34.33,47.15 34.33,45.04 34.39,44.97 34.39,44.68 37.92,41.15 v1(37.97,41.15)
  BOTTOM w0.152: U20.40 18.8,105.14 v1(18.87,105.21)
TCK: length 3.2
  BOTTOM w0.152: U20.15 8.41,102.14 J36.7
TCRIT1: length 33.1
  TOP w0.178: R49.2 R48.2 74.07,123.77 73.56,124.28 73.56,128.3 TP4.1 78.66,124.92 78.66,113.39 74.6,109.32 73.43,109.32 72.9,109.86 U5.4
TCRIT2: length 8.2
  TOP w0.178: U5.7 R47.2 72.82,123.77 72.29,124.31 72.29,126.85 TP3.1
TDI: length 6.4
  BOTTOM w0.152: U20.13 9.91,98.56 J36.3
TDI_FMC: length 18.4
  L10_SIG3 w0.127: J31.1 127.51,55.86 138.46,66.81 138.46,68.61 139.06,69.22 v1(139.06,69.32)
TDIODE+: length 26.7
  L05_SIG1 w0.076: v1(72.52,92.33) 73.01,91.83 73.12,91.83 73.26,91.97 75.4,91.97 76.83,93.41 76.83,99.83 77.62,100.62 77.62,102.69 77.55,102.77 J11.1
  BOTTOM w0.178: v1(70.43,106.53) 70.82,106.14 70.82,105.43 71.31,104.94 77.13,104.94 77.75,104.32 77.75,104.04 J11.1
TDIODE-: length 26.7
  L05_SIG1 w0.076: J11.2 78.02,102.77 77.86,102.62 77.86,100.52 77.08,99.73 77.08,93.31 75.5,91.73 73.36,91.73 73.29,91.66 73.29,91.55 v1(73.79,91.06)
  BOTTOM w0.178: J11.2 78.09,103.7 78.09,104.46 77.27,105.28 71.45,105.28 71.16,105.57 71.16,106.14 v1(71.55,106.53)
TDIODEN: length 2.9
  TOP w0.178: R45.1 71.5,107.59 C37.2 71.63,108.74 U5.3
TDIODEP: length 2.9
  TOP w0.178: U5.2 70.36,108.74 C37.1 70.48,107.59 R43.1
TDO: length 8.4
  BOTTOM w0.152: J36.1 10.69,96.79 U20.12
TDO_FMC: length 20
  L10_SIG3 w0.127: v1(139.06,68.05) 139.06,67.89 139.57,67.39 139.57,65.42 127.51,53.36 J31.2
TEST: length 8.3
  BOTTOM w0.152: U20.22 8.53,105.64 7.67,104.78 6.6,104.78 5.97,104.14 5.97,102.23 J36.8
TMP461_SMBCLK: length 117.3
  TOP w0.178: U5.9 v1(70.36,123.77)
  L08_SIG2 w0.127: v1(70.36,123.77) 70.36,121.67 67.23,118.54 67.23,112.93 66.65,112.34 66.65,107.9 53.14,94.39 53.14,93.9 49.33,90.09 49.33,88.29 48.79,87.76 48.79,46.71 42.77,40.69 37.21,40.69 33.68,44.22 33.68,45.19 31.27,47.6 31.27,50.9 v1(29.21,52.96)
TMP461_SMBDAT: length 117.1
  TOP w0.178: U5.8 v1(71.63,123.77)
  TOP w0.254: v1(27.18,46.61) R133.2
  L08_SIG2 w0.127: v1(27.18,46.61) 30.28,43.51 31.55,43.51 33.38,41.68 35.36,41.68 37.01,40.03 43.08,40.03 49.94,46.89 49.94,86.46 50.7,87.22 50.7,90.32 58.1,97.73 58.68,97.73 58.94,97.99 58.94,98.04 63.3,102.39 63.3,102.92 68.25,107.87 68.25,118.52 71.63,121.89 v1(71.63,123.77)
TMS: length 4.8
  BOTTOM w0.152: U20.14 9.05,101.64 8.76,101.35 8.76,99.95 7.24,98.42
TPM: length 55.8
  L10_SIG3 w0.127: JP4.2 84.3,144.75 84.3,131.39 85.19,130.51 85.19,128.07 82.85,125.73 82.85,113.72 80.72,111.58 80.72,101.45 76.99,97.71 76.99,97.26 76.61,96.88 75.54,96.88 75.06,97.36 v1(75.06,97.41)
TPM_FMC: length 66.5
  TOP w0.152: v1(75.08,98.42) 75.51,98.86 78.51,98.86 78.99,99.34 95.78,99.34 97.64,97.49 120.8,97.49 133.99,84.3 v1(133.99,83.29)
VA19:
  vias: v2(64.64,44.7) v2(64.64,43.56) v2(64.64,42.55) v2(65.71,44.7) v2(65.71,43.56) v2(65.71,42.55) v2(66.88,44.73) v2(66.88,43.59) v2(66.88,42.57) v2(68.15,44.73) v2(68.15,43.59) v2(68.15,42.57) v2(69.37,44.73) v2(69.37,43.59) v2(69.37,42.57) v2(70.59,44.73) v2(70.59,43.59) v2(70.59,42.57) v2(72.01,44.7) v2(72.01,43.56) v2(72.01,42.55) v2(73.08,44.7) v2(73.08,43.56) v2(73.08,42.55) v2(74.24,44.73) v2(74.24,43.59) v2(74.24,42.57) v2(75.51,44.73) v2(75.51,43.59) v2(75.51,42.57) v2(76.73,44.73) v2(76.73,43.59) v2(76.73,42.57) v2(77.95,44.73) v2(77.95,43.59) v2(77.95,42.57) v2(79.12,44.7) v2(79.12,43.56) v2(79.12,42.55) v2(80.19,44.7) v2(80.19,43.56) v2(80.19,42.55) v2(81.36,44.73) v2(81.36,43.59) v2(81.36,42.57) v2(82.63,44.73) v2(82.63,43.59) v2(82.63,42.57) v2(83.85,44.73) v2(83.85,43.59) v2(83.85,42.57) v2(85.06,44.73) v2(85.06,43.59) v2(85.06,42.57) v2(86.21,44.73) v2(86.21,43.59) v2(86.21,42.57) v2(87.35,44.73) v2(87.35,43.59) v2(87.35,42.57)
VADJ_RX: length 62.2
  TOP w0.279: v1(133.99,56.62) 132.36,54.99 R114.1
  L10_SIG3 w0.127: v1(133.99,56.62) v1(135.25,57.89) v1(136.53,56.62) v1(137.79,57.89) 137.29,58.39 137.29,60.53 141.05,64.29 141.05,102.29 137.82,105.51 136.17,105.51 135.84,105.84 135.84,106.5 v1(136.53,107.19)
VBG: length 44
  L08_SIG2 w0.127: J12.2 78.87,134.24 TP2.1 78.87,107.19 71.93,100.25 71.93,96.82 v1(71.25,96.14)
VCM: length 50.8
  TOP w0.305: C15.1 47.68,90.04 v2(48.44,89.28) 47.85,88.7 R15.1
  L05_SIG1 w0.305: v2(52.12,67.16) 51.41,67.16 48.44,70.13 v2(48.44,89.28) 49.66,90.5 49.66,96.77 49.5,96.93 49.5,103.91 53.29,107.7 54.19,107.7 54.62,107.26 v2(55.84,107.26)
VCMO: length 45.8
  L08_SIG2 w0.127: J10.2 81.41,125.68 81.97,125.12 81.97,114.48 82.4,114.05 82.4,111.06 82.02,110.67 82.02,107.57 77.75,103.3 77.75,102.34 73.13,97.71 73.13,95.48 v1(72.52,94.87)
VIO_B_M2C_RX: length 3.5
  TOP w0.279: v1(131.44,56.62) 131.32,56.49 R114.2
  L10_SIG3 w0.127: v1(131.44,56.62) v1(132.72,57.89)
VPHY: length 3
  TOP w0.305: 22.59,43.34 21.99,43.34 v4(21.98,43.35) ; 22.59,43.34 v4(22.59,43.35) ; 22.59,43.34 22.6,43.35 v4(23.67,43.35) ; C158.1 FB1.2
VREGIN: length 33.7
  L10_SIG3 w0.508: JP11.2 9.8,36.04 13.21,36.04 15.52,33.73 29.84,33.73 32.33,36.22 32.33,37.26 v1(31.7,37.9)
  BOTTOM w0.305: U12.50 v1(31.7,37.9) 31.7,37.24 C162.1
VTUNE: length 4.1
  BOTTOM w0.203: U7.55 16.17,128.28 C130.1 R89.2
N18123409: length 24.6
  TOP w0.127: v3(27.51,16.23) v3(27.51,17.23) v3(26.51,17.23) ; v3(27.51,16.23) v3(27.51,15.23) ; v3(27.51,16.23) v3(26.51,16.23) ; v3(25.51,13.23) 25.41,13.33 Q1.8 ; v3(25.51,13.23) v3(26.51,13.23) ; v3(25.51,13.23) v3(25.51,14.23) ; v3(27.51,15.23) v3(27.51,14.23) ; v3(27.51,15.23) 26.54,15.23 v3(26.53,15.22) ; v3(26.51,13.23) v3(27.51,13.23) v3(27.51,14.23) ; v3(26.51,13.23) v3(26.51,14.23) ; v3(25.51,17.23) 25.41,17.14 Q1.5 ; v3(25.51,17.23) v3(25.51,16.23) ; v3(25.51,17.23) v3(26.51,17.23) ; v3(27.51,14.23) v3(26.51,14.23) ; v3(26.51,14.23) v3(25.51,14.23) ; v3(26.51,14.23) 26.51,15.2 v3(26.53,15.22) ; v3(25.51,14.23) v3(25.51,15.23) ; v3(25.51,15.23) v3(25.51,16.23) ; v3(25.51,15.23) 25.52,15.22 v3(26.53,15.22) ; v3(25.51,16.23) v3(26.51,16.23) ; v3(26.51,16.23) v3(26.51,17.23) ; v3(26.51,16.23) 26.53,16.21 v3(26.53,15.22)
  vias: v3(20.43,17.23) v3(20.43,16.23) v3(20.43,15.23) v3(20.43,14.23) v3(20.43,13.23) v3(21.7,17.23) v3(21.7,16.23) v3(21.7,15.23) v3(21.7,14.23) v3(21.7,13.23) v3(22.97,17.23) v3(22.97,16.23) v3(22.97,15.23) v3(22.97,14.23) v3(22.97,13.23) v3(24.24,17.23) v3(24.24,16.23) v3(24.24,15.23) v3(24.24,14.23) v3(24.24,13.23) v3(26.78,11.69) v3(26.78,10.69)
N18340257: length 3.2
  TOP w0.279: D8.1 36.04,20.02 35.26,20.02 R160.2
N19955835: length 3.4
  TOP w0.381: Q1.4 29.77,18.36 29.14,18.99 v2(29.14,20.24)
N20251064: length 1.7
  BOTTOM w0.178: 38.99,130.05 39.65,130.71 C131.2
N20251377: length 30
  L10_SIG3 w0.305: v1(15.14,126.92) 15.14,129.34 19.33,133.53 36.09,133.53 36.78,132.84 v1(36.83,132.84)
  BOTTOM w0.254: v1(36.83,132.84) 36.83,134.09 C134.1 36.68,136.63 TP5.1
N20258125:
  vias: v1(34.16,117.86)
N20447902: length 3.8
  TOP w0.178: D5.2 77.34,122.89 R49.1
N20601243: length 3
  TOP w0.305: D3.1 14.73,61.21 U3.7
N20601382: length 3.1
  TOP w0.305: U3.1 25.02,59.94 D1.1
N20601403: length 2.1
  TOP w0.305: 16.26,57.78 15.37,57.78 D3.2
N20601859: length 1.9
  TOP w0.305: R34.1 25.02,57.66 D1.2
N20602433: length 5.9
  TOP w0.305: U3.5 15.24,63.75 C33.1 R36.2 D4.2
N20603216: length 5.8
  TOP w0.305: D2.2 25.65,63.12 R31.2 C32.1 24.38,62.48 U3.3
N20606076: length 2.7
  BOTTOM w0.152: R35.2 J9.1
N20760406: length 5.9
  TOP w0.305: R180.2 R181.1 C215.2 4.06,78.23 U18.9
N20772111: length 17.1
  TOP w0.381: R163.1 C188.2 68.28,16.03 v2(66.29,16.03)
  BOTTOM w0.381: v2(66.29,16.03) 59.39,22.94 v2(55.63,22.94)
N20772147: length 1.4
  TOP w0.381: R166.2 55.59,27.39 C191.1
N20772149: length 4.4
  TOP w0.381: U15.18 54.36,24 53.85,24.51 53.85,25.27 55.36,25.27 R166.1
N20772252: length 2.2
  TOP w0.305: U15.20 49.71,22.94 R161.2
N20772286: length 3.1
  TOP w0.305: R162.2 R164.2 U15.2
N20772300: length 2
  TOP w0.305: U15.3 R165.2
N20772322: length 2.4
  TOP w0.305: C189.1 52.32,24.26 53.09,23.5 U15.19
N20772348: length 2.1
  TOP w0.381: U15.16 C184.1
N20774965: length 15.4
  L10_SIG3 w0.254: v2(85.47,24.13) 85.52,24.13 87.5,22.15 87.5,14.26 v1(84.19,10.95)
N20775006: length 1.8
  TOP w0.305: C205.1 77.84,9.21 U16.1
N20775018: length 2
  TOP w0.305: U16.15 79.11,26.71 C197.1
N20775020: length 3.1
  TOP w0.305: R173.1 80.31,28.52 C197.2 80.31,25.61 U16.14
N20775032: length 2.6
  TOP w0.305: R171.1 86.75,25.53 U16.9
N20775050: length 2.1
  TOP w0.305: R175.1 85.46,9.03 U16.7
N20775064:
  vias: v2(85.47,25.15)
N20776453:
  vias: v2(71.63,37.72) v2(71.63,36.7) v2(71.63,35.69) v2(71.63,34.67) v2(71.63,33.66) v2(71.63,32.51) v2(72.95,38.3) v2(72.9,37.21) v2(72.9,36.2) v2(72.9,35.18) v2(72.9,34.16) v2(72.9,33.15) v2(72.9,32) v2(74.04,35.56) v2(74.17,39.24) v2(74.17,36.7) v2(74.8,37.97) v2(75.31,39.24) v2(75.31,36.7) v2(75.82,37.97) v2(76.33,39.24) v2(76.33,36.7) v2(76.83,37.97) v2(77.34,39.24) v2(77.34,36.7) v2(77.85,37.97) v2(78.36,39.24) v2(78.36,36.7) v2(78.87,37.97) v2(79.38,39.24) v2(79.38,36.7) v2(79.96,37.92) v2(80.47,39.19) v2(80.47,36.65)
N20810898: length 2.9
  TOP w0.305: PP11.1 55.63,6.6 U15.4
N21127493: length 1.7
  TOP w0.254: U11.4 28.87,44.58 R133.1
N21129355: length 1.8
  TOP w0.305: R118.1 D7.2
N21131028: length 1.7
  TOP w0.305: R148.2 21.68,48.34 v4(23.17,48.34)
N21131030: length 1.9
  BOTTOM w0.152: U12.6 24.4,44.34 v1(24.65,44.59)
N21131895: length 3.7
  BOTTOM w0.152: R157.2 28.07,34.8 R145.2 26.88,36.11 U13.4
N21135480: length 4.2
  BOTTOM w0.381: J32.1 10.52,45.39 R132.2
N21135675: length 4
  BOTTOM w0.178: J32.3 9.49,46.99 9.7,46.78 11.2,46.78 R137.1
N21135677: length 4
  BOTTOM w0.178: R135.1 11.2,46.44 9.74,46.44 9.49,46.19 J32.2
N21135903: length 10.4
  BOTTOM w0.178: R135.2 13.95,46.44 19.22,46.44 20.74,44.92 21.44,44.92 21.52,44.84 U12.7
N21135906: length 10.4
  BOTTOM w0.178: R137.2 13.95,46.78 19.36,46.78 20.88,45.26 21.44,45.26 21.52,45.34 U12.8
N21168383: length 3
  TOP w0.381: R9.2 57.38,99.83 C7.2 57.83,99.38 L3.1
N21168467: length 3
  TOP w0.381: R4.2 59.54,101.98 C4.1 59.99,101.53 L1.1
N21171643: length 1
  TOP w0.381: C5.2 60.8,97.85
N21171649: length 2.9
  TOP w0.381: L2.1 62.48,99.05 C5.1 61.96,99.56 L1.2
N21171654: length 2.9
  TOP w0.381: L3.2 59.81,97.4 C8.2 60.32,96.89 L4.1
N21171729: length 1.1
  TOP w0.381: L2.2 63.4,96.86 C2.1
N21171732: length 1.1
  TOP w0.381: L4.2 62.5,95.97 C14.1
N21175089: length 1.9
  BOTTOM w0.152: R29.2 J7.1
N21175349: length 1.9
  BOTTOM w0.152: R30.2 J8.1
N21187119: length 0.3
  BOTTOM w0.305: C126.1 v1(72.52,85.98)
N21187126: length 0.3
  BOTTOM w0.305: C125.1 v1(75.06,87.25)
N21187133: length 0.3
  BOTTOM w0.305: C124.1 v1(78.87,93.6)
N21188308: length 0.3
  BOTTOM w0.305: C116.1 v1(78.87,77.09)
N21188315: length 0.3
  BOTTOM w0.305: C115.1 v1(75.06,83.44)
N21188322: length 0.3
  BOTTOM w0.305: C114.1 v1(72.52,84.71)
N21202974: length 0.1
  BOTTOM w0.305: R51.1 v1(73.79,74.55)
N21203641:
  vias: v1(73.79,92.33)
N21203646:
  vias: v1(75.06,91.06)
N21203848: length 0.1
  BOTTOM w0.305: R42.2 v1(73.79,94.87)
N21203855: length 0.1
  BOTTOM w0.305: R42.1 v1(73.79,93.6)
N21203893: length 0.4
  BOTTOM w0.305: R44.2 v1(71.25,94.87)
N21203895: length 0.4
  BOTTOM w0.305: R44.1 v1(72.52,93.6)
N21228014:
  vias: v1(91.57,85.98)
N21228016:
  vias: v1(92.84,85.98)
N21228048:
  vias: v1(91.57,84.71)
N21228050:
  vias: v1(92.84,84.71)
N21241287: length 2.3
  TOP w0.381: 45.53,112.94 R10.1 C6.1
N21267772: length 3
  TOP w0.381: L7.1 60.01,69.15 C21.2 59.56,68.7 R23.2
N21267797: length 3
  TOP w0.381: L5.1 57.85,71.31 C19.1 57.41,70.86 R19.2
N21267893: length 1
  TOP w0.381: C22.1 61.54,72.11 C20.2
N21267903: length 2.9
  TOP w0.381: L6.1 60.34,73.8 C20.1 59.83,73.28 L5.2
N21267907: length 2.9
  TOP w0.381: L8.1 62.5,71.63 C22.2 62,71.13 L7.2
N21267936: length 1.1
  TOP w0.381: L6.2 62.52,74.72 C17.1
N21267939: length 1.1
  TOP w0.381: C24.1 63.42,73.82 L8.2
N21306634: length 6.2
  TOP w0.305: R183.1 42.42,19.18 R182.2 C226.2 44.32,17.14 U19.9
N21310593: length 3.2
  BOTTOM w0.305: U7.42 25.28,120.53 25.15,120.4 C153.2
N21313753: length 11.1
  BOTTOM w0.381: v1(20.32,141.99) 23.42,141.99 24.66,143.23 R184.2 27.43,142.98 R91.1 R93.2 C128.2
N21313758: length 3.9
  BOTTOM w0.381: C135.2 28.45,139.7 R93.1 28.57,140.84 R96.1 28.57,142.98 R185.1
N21321417: length 3.1
  TOP w0.279: C137.1 R99.1 R97.2 L9.1
N21321463: length 3.3
  BOTTOM w0.178: U7.37 27.79,120.54 27.85,120.48 27.85,119.16 v5(27.43,118.75)
N21321475: length 3.3
  BOTTOM w0.178: U7.36 28.29,120.54 28.19,120.44 28.19,119.13 v5(28.57,118.75)
N21324767: length 3.4
  BOTTOM w0.381: Y1.5 27.3,144.93 R184.1 26.01,144.81 R92.2
N21324772: length 3.4
  BOTTOM w0.381: Y1.4 28.57,145.06 R185.2 30,144.81 R94.2
N21375599: length 3.3
  TOP w0.279: C142.1 R104.1 R100.2 L10.1
N21375615: length 3.6
  BOTTOM w0.178: v5(36.58,126.11) 36.22,126.47 35.46,126.47 35.37,126.38 34.63,126.38 34.53,126.28 U7.30
N21375619: length 3.6
  BOTTOM w0.178: U7.29 34.53,126.78 34.59,126.72 35.23,126.72 35.32,126.81 36.26,126.81 v5(36.58,127.13)
N21375683: length 20.7
  BOTTOM w0.381: C138.2 40.46,125.09 46.8,131.44 54.6,131.44 v1(54.61,131.44)
N21375685: length 20.7
  BOTTOM w0.381: C144.2 38.58,128.14 45.97,135.53 v1(45.97,143.76)
N21382849:
  vias: v4(18.19,127.28) v4(18.88,127.28) v4(19.63,127.28)
N21382882:
  vias: v4(24.28,122.58) v4(24.28,121.74) v4(24.28,120.98)
N21382945: length 3.3
  BOTTOM w0.203: U7.56 16.89,128.78 16.46,129.21 16.46,129.34 16.15,129.64 C150.1
N21382968:
  vias: v4(18.01,130.28) v4(18.72,130.28) v4(19.79,130.28)
N21391760:
  vias: v4(28.78,137.06) v4(28.78,136.32) v4(28.78,135.38)
N21391777:
  vias: v4(25.27,136.91) v4(25.27,135.89) v4(25.27,135.25)
N21397866:
  vias: v4(29.29,122.66) v4(29.29,121.77) v4(29.29,121.01)
N21398145:
  vias: v4(27.28,136.88) v4(27.28,136.12) v4(27.28,135.43)
N21398455:
  vias: v4(32.56,130.78) v4(33.1,130.78) v4(33.99,130.78)
N21398481:
  vias: v4(32.46,128.78) v4(33.19,128.78) v4(34.04,128.78)
N21398674:
  vias: v4(18.03,129.29) v4(18.82,129.29) v4(19.53,129.29)
N21398700:
  vias: v4(25.78,122.76) v4(25.78,121.97) v4(25.78,121.06)
N21435177:
  vias: v2(70.87,30.1) v2(70.87,29.08) v2(70.87,28.07) v2(71.88,30.1) v2(71.88,29.08) v2(71.88,28.07) v2(72.9,30.1) v2(72.9,29.08) v2(72.9,28.07) v2(76.71,6.99) v2(76.71,5.71) v2(77.85,6.99) v2(77.85,5.71) v2(78.99,6.99) v2(78.99,5.71) v2(80.14,6.99) v2(80.14,5.71)
N21445987: length 6.5
  L10_SIG3 w0.127: v1(139.06,56.62) v1(140.34,57.89) v1(139.06,59.16) 138.58,59.64 138.58,61.21 v1(139.06,61.7)
N21446161: length 81.1
  L10_SIG3 w0.127: v1(139.06,106.15) 139.73,105.49 141.67,105.49 143.79,103.37 143.79,56.31 140.37,52.9 136.77,52.9 136.33,52.45 130.28,52.45 128.75,50.93 123.62,50.93 122.38,52.17 122.38,54.31 J29.1
N21451420: length 4.5
  TOP w0.178: C53.1 107.44,117.25 R61.1 107.23,117.04 106.48,117.04 105.4,115.96 105.23,115.96 105.08,116.1 U6.26
N21451422: length 4.5
  TOP w0.178: C54.1 107.44,116.48 R62.1 107.23,116.69 106.62,116.69 105.54,115.61 105.18,115.61 105.03,115.47 U6.25
N21451444: length 3.4
  TOP w0.178: U6.24 105.05,114.83 105.2,114.69 105.75,114.69 106.1,115.04 106.5,115.04 R67.1 106.68,115.21 C57.1
N21451446: length 3.4
  TOP w0.178: U6.23 105.03,114.2 105.18,114.34 105.89,114.34 106.21,114.67 106.46,114.67 R68.1 106.68,114.45 C58.1
N21451502: length 38.5
  TOP w0.178: v5(106.63,109.93) 106.47,110.09 106.06,110.09 105.68,110.47 105.68,111.63 105.5,111.8 105.25,111.8 105.11,111.66 U6.19
  BOTTOM w0.178: v5(106.63,109.93) 106.79,110.09 107.71,110.09 113.08,104.72 113.08,100.09 112.18,99.19 112.18,97.08 113.08,96.17 113.08,93.32 112.18,92.42 112.18,88.99 117.42,83.75 118.06,83.75 118.24,83.57 v1(118.24,82.93)
N21451579: length 11.3
  TOP w0.178: JP10.2 84.94,120.02 88.85,116.1 U6.2
N21451692: length 43.8
  TOP w0.178: v4(87.45,113.54) 87.57,113.42 88.99,113.42 89.14,113.56 U6.6
  BOTTOM w0.178: v4(98.88,84.91) 98.88,84.9 99.69,84.09 101,84.09 102.04,85.13 102.04,93.81 85.34,110.51 85.34,112.68 86.07,113.4 87.31,113.4 v4(87.45,113.54)
N21451698: length 43.8
  TOP w0.178: v4(87.45,112.93) 87.6,113.07 88.99,113.07 89.14,112.93 U6.7
  BOTTOM w0.178: v4(98.88,82.93) 99.69,83.74 101.14,83.74 102.39,84.99 102.39,93.95 85.69,110.66 85.69,112.53 86.21,113.06 87.33,113.06 v4(87.45,112.93)
N21453692:
  vias: v1(100.84,25.53) v1(100.84,24.64) v1(100.84,23.75) v1(100.84,22.86) v1(100.84,21.97)
N21453823: length 9.1
  TOP w0.381: v1(100.84,12.19) 100.84,13.97 99.57,15.24 99.57,17.53 100.71,18.67 R179.1 R177.2
N21482374: length 22.4
  L10_SIG3 w0.254: J34.1 90.42,10.49 93.8,13.87 94.77,13.87 102.87,21.97 v1(103.38,21.97)
  BOTTOM w0.381: U17.5 v1(103.38,21.97)
N21491465: length 9.4
  BOTTOM w0.152: R130.2 62.08,26.82 61.44,26.82 60.07,28.19 60.07,32.21 59.6,32.68 U9.6
N21491508: length 8.5
  BOTTOM w0.152: U9.5 59.99,33.33 60.63,32.69 60.63,29.49 61.67,28.45 62.1,28.45 R128.2
N21491543: length 7.5
  BOTTOM w0.152: R121.1 61.98,30.23 61.62,30.23 61.24,30.61 61.24,32.82 60.08,33.98 U9.4
N21491580: length 6.3
  BOTTOM w0.152: R116.2 62.87,31.93 60.16,34.63 U9.3
N21491663: length 1
  TOP w0.305: R126.2 R127.1
N21491825: length 3.2
  BOTTOM w0.152: R122.1 50.71,34.63 U9.14
N21491829: length 3
  BOTTOM w0.152: R123.1 50.22,33.98 U9.13
N21491833: length 3
  BOTTOM w0.152: U9.12 50.35,33.33 R124.1
N21491837: length 3.2
  BOTTOM w0.152: R125.1 50.84,32.68 U9.11
  vias: v1(53.59,32.69)
N21491881:
  vias: v1(53.59,31.37)
N21538078: length 2.3
  TOP w0.381: 47.44,59.45 R21.1 R20.1
N21540492: length 43.8
  TOP w0.178: U6.3 89.14,115.47 88.99,115.32 87.6,115.32 v4(87.45,115.47)
  BOTTOM w0.178: v4(98.88,87.5) 98.89,87.5 99.72,86.68 100.64,86.68 100.85,86.88 100.85,92.77 83.58,110.04 83.58,113.5 85.41,115.34 87.32,115.34 v4(87.45,115.47)
N21540508: length 43.8
  TOP w0.178: v4(87.45,114.86) 87.57,114.98 88.99,114.98 89.14,114.83 U6.4
  BOTTOM w0.178: v4(98.88,85.52) 99.69,86.33 100.79,86.33 101.19,86.74 101.19,92.91 83.92,110.19 83.92,113.36 85.56,114.99 87.32,114.99 v4(87.45,114.86)
N21563907: length 38.5
  TOP w0.178: v5(106.63,110.59) 106.47,110.43 106.2,110.43 106.02,110.61 106.02,111.77 105.64,112.15 105.25,112.15 105.11,112.29 U6.20
  BOTTOM w0.178: v5(106.63,110.59) 106.79,110.43 107.85,110.43 113.42,104.86 113.42,99.95 112.52,99.05 112.52,97.22 113.42,96.32 113.42,93.18 112.52,92.28 112.52,89.13 117.56,84.09 118.06,84.09 118.24,84.27 v1(118.24,84.91)
N21564155: length 38.5
  TOP w0.178: U6.21 105.05,112.93 105.2,113.07 106.05,113.07 106.53,112.6 107.26,112.6 v5(107.39,112.47)
  BOTTOM w0.178: v5(107.39,112.47) 107.55,112.63 110.1,112.63 116.65,106.08 116.65,104.01 115.7,103.06 115.7,99.91 116.55,99.06 116.55,97.62 115.7,96.77 115.7,88.32 117.45,86.56 117.45,86.56 117.67,86.34 118.06,86.34 118.24,86.16 v1(118.24,85.52)
N21564157: length 38.5
  TOP w0.178: U6.22 105.05,113.56 105.2,113.42 106.19,113.42 106.63,112.98 107.24,112.98 v5(107.39,113.13)
  BOTTOM w0.178: v5(107.39,113.13) 107.55,112.97 110.24,112.97 116.99,106.23 116.99,103.87 116.04,102.91 116.04,100.05 116.89,99.2 116.89,97.48 116.04,96.63 116.04,88.46 117.79,86.71 117.79,86.7 117.81,86.68 118.06,86.68 118.24,86.86 v1(118.24,87.5)
N21594563: length 16.2
  L10_SIG3 w0.254: v1(104.65,22.86) 104.65,21.21 102.06,18.62 101.17,18.62 94.36,11.81 TP16.1
N21602890: length 8.8
  BOTTOM w0.381: J24.1 31.17,150.06 27.05,150.06 26.04,149.05 Y1.1
